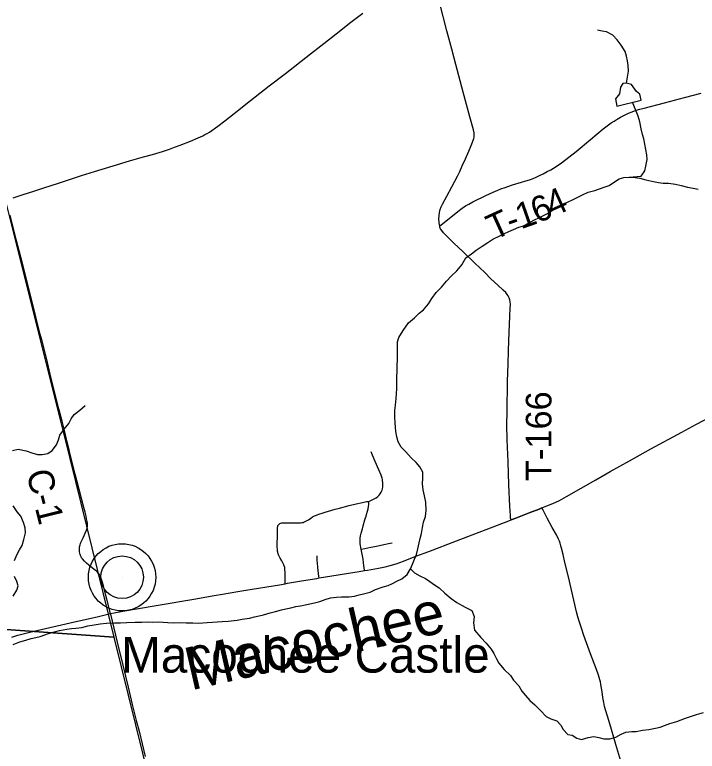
# Model space of a CAD drawing. Extents: x 0 to 1101, y 0 to 440.
# Drawn here: x 842.658 to 844.169, y 377.521 to 379.151 of the extents above; entities that cross this region are included whole.
import ezdxf

# ---------------------------------------------------------------- set-up
doc = ezdxf.new("R2010")
doc.units = 0
for name, color, linetype in [('GM_X_County_Road', 7, 'Continuous'), ('GM_X_County_Road_Text', 7, 'Continuous'), ('GM_X_Minor_Lake', 7, 'Continuous'), ('GM_X_Minor_River', 7, 'Continuous'), ('GM_X_Minor_River_Text', 7, 'Continuous'), ('GM_X_Section', 7, 'Continuous'), ('GM_X_State_Route', 7, 'Continuous'), ('GM_X_Township_Road', 7, 'Continuous'), ('GM_X_Township_Road_Text', 7, 'Continuous'), ('GM_X_Unincorporated', 7, 'Continuous'), ('GM_X_Unincorporated_Location', 7, 'Continuous'), ('GM_X_Unincorporated_Text', 7, 'Continuous')]:
    doc.layers.add(name, color=color, linetype=linetype)

msp = doc.modelspace()

# ---------------------------------------------------------------- linework, layer by layer
at = {"layer": 'GM_X_County_Road'}
for points in [[(842.6544, 378.7458), (842.6772, 378.7533), (842.7008, 378.761), (842.7226, 378.7682), (842.7551, 378.7789), (842.7769, 378.7861), (842.8058, 378.7954), (842.8348, 378.8047), (842.8764, 378.8172), (842.9121, 378.8279), (842.9432, 378.8368), (842.9629, 378.8424), (842.985, 378.8489), (843.0004, 378.8538), (843.0121, 378.858), (843.0243, 378.8626), (843.0475, 378.8717), (843.0641, 378.8787), (843.0691, 378.881), (843.0742, 378.8835), (843.0788, 378.886), (843.0841, 378.8889), (843.0893, 378.8919), (843.0947, 378.8955), (843.1024, 378.9008), (843.1079, 378.9049), (843.1232, 378.9166), (843.1436, 378.9329), (843.1801, 378.9618), (843.2214, 378.9938), (843.2572, 379.0217), (843.3125, 379.0649), (843.3354, 379.083), (843.376, 379.1144), (843.3992, 379.1325), (843.4288, 379.1552)], [(842.8187, 378.0282), (842.8185, 378.0298), (842.8174, 378.0359), (842.8161, 378.0416), (842.814, 378.05), (842.8112, 378.0605), (842.7957, 378.1207), (842.7921, 378.1345), (842.7812, 378.1783), (842.7787, 378.1883), (842.7743, 378.2056), (842.768, 378.2312), (842.763, 378.2515), (842.7561, 378.2789), (842.7369, 378.3557), (842.7289, 378.3882), (842.7181, 378.4316), (842.7147, 378.4442), (842.7088, 378.4671), (842.7016, 378.4952), (842.6907, 378.5397), (842.6746, 378.6038), (842.6616, 378.6538), (842.6482, 378.7076)], [(842.87, 377.8257), (842.862, 377.8576), (842.8592, 377.8686), (842.8545, 377.8871), (842.8518, 377.8972), (842.8498, 377.9037), (842.848, 377.9081), (842.8469, 377.9099), (842.8455, 377.9122), (842.8444, 377.914), (842.8431, 377.9156), (842.8414, 377.9174), (842.8393, 377.9194), (842.8341, 377.9236), (842.822, 377.9333), (842.8173, 377.9373), (842.8125, 377.9419), (842.8082, 377.9467), (842.8063, 377.9492), (842.8049, 377.9516), (842.8037, 377.9541), (842.8027, 377.9569), (842.802, 377.9596), (842.8017, 377.9622), (842.8014, 377.9646), (842.8013, 377.9675), (842.8014, 377.9698), (842.8018, 377.9733), (842.8028, 377.9782), (842.8037, 377.981), (842.8047, 377.9833), (842.8068, 377.9879), (842.8094, 377.9932), (842.8143, 378.0041), (842.8171, 378.0105), (842.8185, 378.0147), (842.819, 378.0175), (842.8193, 378.0195), (842.8193, 378.0217), (842.8192, 378.0237), (842.819, 378.0267), (842.8187, 378.0282)]]:
    msp.add_lwpolyline(points, dxfattribs=at)
at = {"layer": 'GM_X_Minor_Lake'}
for points in [[(844.0447, 378.9623), (844.0422, 378.9757), (844.0344, 378.9814), (844.0232, 378.9968), (844.0119, 379), (844.0039, 378.9989), (843.9989, 378.991), (843.9968, 378.9766), (843.9879, 378.9654), (843.9911, 378.9494)], [(843.9911, 378.9494), (844.0447, 378.9623)]]:
    msp.add_lwpolyline(points, dxfattribs=at)
at = {"layer": 'GM_X_Minor_River'}
for points in [[(844.0121, 378.9999), (844.0164, 379.0268), (844.0158, 379.0394), (844.0148, 379.0493), (844.0123, 379.0595), (844.0091, 379.0698), (844.0006, 379.084), (843.992, 379.0958), (843.9819, 379.1059), (843.9684, 379.1136), (843.9582, 379.1153), (843.948, 379.1173)], [(844.0184, 378.7916), (844.045, 378.7942), (844.0527, 378.8063), (844.0551, 378.8161), (844.0584, 378.8309), (844.0574, 378.8415), (844.0549, 378.8529), (844.0507, 378.8765), (844.0478, 378.886), (844.0449, 378.899), (844.0421, 378.9142), (844.0381, 378.9271), (844.0259, 378.9578)], [(843.3568, 377.8604), (843.3701, 377.8621), (843.3815, 377.8627), (843.3985, 377.8632), (843.4099, 377.8646), (843.4206, 377.8671), (843.4301, 377.8696), (843.4449, 377.8732), (843.4567, 377.8788), (843.4739, 377.885), (843.4845, 377.8882), (843.4941, 377.8927), (843.504, 377.8978), (843.5147, 377.9026), (843.527, 377.9123), (843.5343, 377.9251), (843.539, 377.9349), (843.5434, 377.9462), (843.5473, 377.9568), (843.5505, 377.9689), (843.5533, 377.9821), (843.5557, 377.992), (843.5586, 378.0033), (843.5606, 378.0166), (843.5631, 378.0279), (843.5671, 378.0411), (843.5688, 378.054), (843.5679, 378.0726), (843.5654, 378.0863), (843.5622, 378.1), (843.5609, 378.1129), (843.5618, 378.1254), (843.5612, 378.1387), (843.5546, 378.1509), (843.5464, 378.1605), (843.5355, 378.1709), (843.524, 378.1836), (843.5139, 378.1944), (843.5072, 378.2059), (843.504, 378.2169), (843.5015, 378.2287), (843.5013, 378.2386), (843.5003, 378.2481), (843.4997, 378.2617), (843.4999, 378.2754), (843.5008, 378.2871), (843.5025, 378.3019), (843.5034, 378.3125), (843.5036, 378.3239), (843.5042, 378.3383), (843.5043, 378.3489), (843.5049, 378.363), (843.5054, 378.3994), (843.5053, 378.4142), (843.5058, 378.4275), (843.5082, 378.4373), (843.5179, 378.4523), (843.5299, 378.4692), (843.5433, 378.4808), (843.5533, 378.4905), (843.5633, 378.4984), (843.5737, 378.5115), (843.5811, 378.5232), (843.5911, 378.5363), (843.6027, 378.5487), (843.6142, 378.5614), (843.6242, 378.573), (843.6365, 378.5846), (843.6477, 378.5981), (843.657, 378.6136), (843.6689, 378.6221), (843.6792, 378.63), (843.6926, 378.6393), (843.7052, 378.6471), (843.7163, 378.6545), (843.732, 378.6619), (843.7423, 378.6674), (843.7518, 378.6718), (843.7621, 378.6763), (843.7739, 378.681), (843.7842, 378.6843), (843.7953, 378.6898), (843.8075, 378.6965), (843.8201, 378.7028), (843.8357, 378.7105), (843.8457, 378.7169), (843.8568, 378.7239), (843.869, 378.7306), (843.8831, 378.7376), (843.893, 378.7416), (843.9033, 378.7468), (843.9152, 378.7531), (843.9278, 378.7586), (843.9422, 378.7626), (843.9525, 378.7663), (843.9628, 378.7695), (843.9742, 378.7736), (843.9861, 378.7814), (843.9964, 378.7881), (844.0063, 378.791), (844.0184, 378.7916)], [(844.0184, 378.7916), (844.0317, 378.791), (844.0419, 378.7894), (844.0551, 378.7861), (844.0687, 378.7833), (844.083, 378.7801), (844.0933, 378.7788), (844.105, 378.7783), (844.1205, 378.7762), (844.1334, 378.7737), (844.1473, 378.7697), (844.1602, 378.7677), (844.1707, 378.7652)], [(842.6531, 378.1867), (842.666, 378.1895), (842.6834, 378.1862), (842.6959, 378.1819), (842.7083, 378.1783), (842.7189, 378.1782), (842.7311, 378.1803), (842.7407, 378.187), (842.7507, 378.1993), (842.7554, 378.2107), (842.7582, 378.2205), (842.7679, 378.234), (842.7783, 378.2464), (842.783, 378.2569), (842.7899, 378.2667), (842.8026, 378.2764), (842.8141, 378.2861)], [(842.6576, 377.943), (842.6631, 377.9562), (842.6686, 377.9668), (842.6748, 377.9769), (842.6784, 377.9898), (842.682, 378.0049), (842.681, 378.0156), (842.6774, 378.0274), (842.6719, 378.0415), (842.6633, 378.0511), (842.6544, 378.0641)], [(843.5343, 377.9251), (843.5433, 377.9159), (843.555, 377.9093), (843.5674, 377.9038), (843.5771, 377.8972), (843.5876, 377.8895), (843.5974, 377.8825), (843.6101, 377.8713), (843.6244, 377.8594), (843.6367, 377.8501), (843.6469, 377.8443), (843.657, 377.8392), (843.6698, 377.8326), (843.6753, 377.8192), (843.674, 377.8056), (843.676, 377.7892), (843.6902, 377.7731), (843.7014, 377.7601), (843.713, 377.7474), (843.7189, 377.7374), (843.7244, 377.7256), (843.7299, 377.7157), (843.7419, 377.7022), (843.7553, 377.6884), (843.7624, 377.6784), (843.774, 377.6661), (843.781, 377.6539), (843.7884, 377.6443), (843.7981, 377.6332), (843.8097, 377.6235), (843.8217, 377.6112), (843.8348, 377.5981), (843.8445, 377.5927), (843.8581, 377.5887), (843.8671, 377.5791), (843.8722, 377.5692), (843.8823, 377.5584), (843.8921, 377.5564), (843.9027, 377.5502), (843.9125, 377.5474), (843.9277, 377.5514), (843.9402, 377.5535), (843.9512, 377.5514), (843.9621, 377.5482), (843.9754, 377.5484), (843.9887, 377.5524), (844.0002, 377.5591), (844.0112, 377.5631), (844.0245, 377.5649), (844.034, 377.5651), (844.0477, 377.5676), (844.0621, 377.5693), (844.0765, 377.5725), (844.0868, 377.5743), (844.0963, 377.5779), (844.1081, 377.5827), (844.1237, 377.5867), (844.1333, 377.5907), (844.1432, 377.5944), (844.1561, 377.5991), (844.1675, 377.6024), (844.1831, 377.6068)], [(842.6546, 377.8642), (842.6627, 377.8773), (842.6655, 377.8872), (842.663, 377.8971), (842.6575, 377.9081)], [(842.655, 377.7576), (842.6695, 377.763), (842.6828, 377.767), (842.6942, 377.7707), (842.7052, 377.7732), (842.7147, 377.7749), (842.733, 377.7815), (842.7463, 377.7851), (842.7574, 377.7887), (842.7737, 377.7912), (842.784, 377.7925), (842.7935, 377.7936), (842.8067, 377.7953), (842.82, 377.7985), (842.8337, 377.801), (842.847, 377.8034), (842.8611, 377.8044), (842.8793, 377.8052), (842.8925, 377.8054), (842.9062, 377.8064), (842.9251, 377.8069), (842.9396, 377.8071), (842.9513, 377.8073), (842.9623, 377.8071), (842.9767, 377.8073), (842.9865, 377.8068), (842.9971, 377.8062), (843.0096, 377.8057), (843.0248, 377.8062), (843.0373, 377.8057), (843.0521, 377.8051), (843.0646, 377.8049), (843.0843, 377.8058), (843.0961, 377.8068), (843.1063, 377.8074), (843.1177, 377.808), (843.1306, 377.8089), (843.1503, 377.8109), (843.1614, 377.8134), (843.1781, 377.8159), (843.1891, 377.8187), (843.199, 377.8209), (843.2085, 377.823), (843.2233, 377.8274), (843.2351, 377.8302), (843.2484, 377.8342), (843.2583, 377.836), (843.269, 377.8385), (843.2807, 377.8414), (843.2906, 377.8427), (843.3051, 377.8463), (843.3218, 377.8495), (843.3336, 377.8528), (843.345, 377.8572), (843.3568, 377.8604)]]:
    msp.add_lwpolyline(points, dxfattribs=at)
at = {"layer": 'GM_X_Section'}
for points in [[(842.5276, 378.7981), (842.6237, 378.792), (842.7799, 378.1693), (842.8774, 377.7736), (842.4313, 377.8052)], [(842.4313, 377.8052), (842.8774, 377.7736), (842.9572, 377.4512), (843.1456, 376.7087), (842.3392, 376.7881)]]:
    msp.add_lwpolyline(points, close=True, dxfattribs=at)
at = {"layer": 'GM_X_State_Route'}
for points in [[(843.8248, 378.0596), (843.8362, 378.064), (843.8492, 378.0695), (843.8637, 378.0764), (843.8798, 378.0847), (843.9441, 378.1219), (843.9586, 378.1301), (843.9764, 378.14), (844.0191, 378.1642), (844.0664, 378.1904), (844.1346, 378.2277), (844.1671, 378.2451), (844.2149, 378.2702)], [(843.7567, 378.033), (843.7674, 378.0372), (843.7967, 378.0485), (843.8191, 378.0573), (843.8248, 378.0596)], [(842.87, 377.8257), (842.878, 377.8272), (842.8973, 377.831), (842.9711, 377.8434), (843.0549, 377.8576), (843.0994, 377.8655), (843.1178, 377.8687), (843.1517, 377.8744), (843.1697, 377.8775), (843.244, 377.8896), (843.2567, 377.8919), (843.2622, 377.8929), (843.2929, 377.898), (843.3266, 377.9038), (843.3319, 377.9047), (843.4208, 377.919), (843.4326, 377.921), (843.4394, 377.9221), (843.4636, 377.9263), (843.4778, 377.9293), (843.4895, 377.9325), (843.5022, 377.9362), (843.5185, 377.9422), (843.5462, 377.9527), (843.5746, 377.9633), (843.6358, 377.9866), (843.7519, 378.031), (843.7567, 378.033)], [(842.652, 377.7736), (842.665, 377.7777), (842.6824, 377.7825), (842.7073, 377.7884), (842.7806, 377.805), (842.8435, 377.8196), (842.87, 377.8257), (842.8702, 377.8247)], [(842.8702, 377.8247), (842.8849, 377.7626), (842.8973, 377.7113), (842.909, 377.663), (842.9183, 377.6243), (842.9273, 377.5895), (842.9333, 377.5653), (842.9467, 377.5091)]]:
    msp.add_lwpolyline(points, dxfattribs=at)
at = {"layer": 'GM_X_Township_Road'}
for points in [[(843.651, 378.98), (843.6346, 379.041), (843.6254, 379.0752), (843.6148, 379.1161), (843.5988, 379.1761)], [(843.7567, 378.033), (843.7559, 378.0367), (843.7556, 378.0399), (843.7553, 378.043), (843.7538, 378.0633), (843.7517, 378.1111), (843.7505, 378.1615), (843.7484, 378.2105), (843.7477, 378.2434), (843.7481, 378.2726), (843.7491, 378.3406), (843.7503, 378.3782), (843.7512, 378.4073), (843.7519, 378.4297), (843.7526, 378.4482), (843.7542, 378.4843), (843.7551, 378.5019), (843.7553, 378.51), (843.7549, 378.5161), (843.7539, 378.5207), (843.7525, 378.525), (843.7503, 378.529), (843.7484, 378.532), (843.7449, 378.5363), (843.7392, 378.5419), (843.7276, 378.5531), (843.7124, 378.567), (843.6984, 378.5811), (843.6765, 378.6017), (843.6506, 378.6264), (843.6305, 378.6457), (843.613, 378.6626), (843.6075, 378.6686), (843.6033, 378.6741), (843.6009, 378.6779), (843.5994, 378.6814), (843.5988, 378.6839), (843.5983, 378.6857), (843.5974, 378.692), (843.5971, 378.6989), (843.5975, 378.707), (843.5985, 378.7139), (843.6, 378.72), (843.6021, 378.7259), (843.605, 378.7322), (843.6144, 378.7498), (843.6256, 378.7704), (843.6379, 378.7941), (843.6431, 378.8047), (843.6489, 378.817), (843.6557, 378.8323), (843.6633, 378.8492), (843.6687, 378.8617), (843.6717, 378.8691), (843.6744, 378.8773), (843.6752, 378.8808), (843.6753, 378.885), (843.6748, 378.8904), (843.6734, 378.897), (843.6656, 378.9258), (843.651, 378.98)], [(843.5988, 378.6839), (843.6012, 378.6858), (843.6427, 378.7191), (843.6485, 378.7233), (843.6561, 378.7282), (843.663, 378.7323), (843.6723, 378.7374), (843.7008, 378.7513), (843.717, 378.7585), (843.7277, 378.7632), (843.7344, 378.7659), (843.7436, 378.7694), (843.7498, 378.7716), (843.76, 378.7747), (843.7798, 378.7808), (843.7895, 378.7836), (843.7976, 378.7861), (843.8056, 378.789), (843.8121, 378.792), (843.8195, 378.7953), (843.8281, 378.7996), (843.8367, 378.8042), (843.8445, 378.8084), (843.8504, 378.8118), (843.8564, 378.8155), (843.8684, 378.8238), (843.9008, 378.8491), (843.9328, 378.875), (843.961, 378.8986), (843.9695, 378.9055), (843.9787, 378.9121), (843.9848, 378.9161), (843.9917, 378.9204), (843.9989, 378.9245), (844.0052, 378.928), (844.0108, 378.9307), (844.0169, 378.9334), (844.0246, 378.9365), (844.034, 378.9399), (844.042, 378.9424), (844.0513, 378.945), (844.0963, 378.9565), (844.1409, 378.968), (844.1777, 378.9775)], [(843.2567, 377.8919), (843.2567, 377.895), (843.2568, 377.9012), (843.2569, 377.9118), (843.2569, 377.9171), (843.2564, 377.9236), (843.2558, 377.9275), (843.2548, 377.9316), (843.2539, 377.9339), (843.2527, 377.9366), (843.2495, 377.9425), (843.2456, 377.9487), (843.2433, 377.9529), (843.2418, 377.9559), (843.2412, 377.9581), (843.2403, 377.962), (843.2401, 377.9637), (843.2399, 377.9652), (843.2396, 377.9681), (843.2394, 377.9731), (843.2397, 378.0043), (843.2396, 378.0111), (843.2397, 378.0142), (843.24, 378.0168), (843.2402, 378.0185), (843.2408, 378.0208), (843.2419, 378.0224), (843.2432, 378.0238), (843.245, 378.025), (843.2474, 378.026), (843.2492, 378.0265), (843.2515, 378.0268), (843.2529, 378.0269), (843.2561, 378.027), (843.2676, 378.0268), (843.2856, 378.0265), (843.2909, 378.0268), (843.2937, 378.0271), (843.2964, 378.0278), (843.2989, 378.0287), (843.3014, 378.0299), (843.3042, 378.0314), (843.3081, 378.0336), (843.3133, 378.0371), (843.3174, 378.0397), (843.322, 378.042), (843.326, 378.0438), (843.3311, 378.0461), (843.3384, 378.0484), (843.3452, 378.0507), (843.3526, 378.0529), (843.3598, 378.0548), (843.3678, 378.057), (843.3768, 378.0593), (843.3985, 378.065), (843.4141, 378.0687), (843.4276, 378.0718), (843.4369, 378.0737), (843.4415, 378.0743), (843.4453, 378.0754), (843.4481, 378.0766), (843.4512, 378.0781), (843.4553, 378.0805), (843.4584, 378.0824), (843.4617, 378.0848), (843.4631, 378.0862), (843.465, 378.0883), (843.4672, 378.0911), (843.4693, 378.0945), (843.4712, 378.0989), (843.4723, 378.1022), (843.4729, 378.1062), (843.4732, 378.1101), (843.473, 378.115), (843.4723, 378.1207), (843.4719, 378.123), (843.4713, 378.1254), (843.4705, 378.128), (843.469, 378.1324), (843.4642, 378.1438), (843.4613, 378.1505), (843.4535, 378.1678), (843.4486, 378.1801), (843.4472, 378.1836)], [(843.4326, 377.921), (843.4317, 377.9276), (843.4312, 377.9312), (843.4291, 377.9461), (843.4258, 377.9647), (843.4251, 377.9682), (843.4242, 377.9723), (843.4233, 377.9769), (843.423, 377.9801), (843.4227, 377.9823), (843.4226, 377.9851), (843.4226, 377.988), (843.4229, 377.9928), (843.4238, 377.998), (843.4252, 378.0035), (843.4276, 378.0137), (843.4294, 378.0203), (843.4334, 378.0332), (843.4349, 378.038), (843.436, 378.0415), (843.437, 378.0451), (843.439, 378.0523), (843.4403, 378.0577), (843.4411, 378.0626), (843.4417, 378.067), (843.4419, 378.0704), (843.4415, 378.0743)], [(843.8248, 378.0596), (843.8191, 378.0573), (843.7967, 378.0485), (843.7674, 378.0372), (843.7567, 378.033)], [(843.9828, 377.5564), (843.9806, 377.5642), (843.9776, 377.5743), (843.97, 377.5984), (843.9665, 377.6104), (843.9639, 377.6203), (843.9622, 377.6288), (843.9603, 377.6398), (843.9583, 377.6526), (843.9558, 377.6686), (843.9547, 377.6744), (843.9536, 377.6789), (843.9505, 377.6897), (843.9461, 377.7019), (843.9324, 377.7365), (843.9182, 377.7773), (843.9124, 377.7934), (843.9072, 377.8088), (843.9046, 377.8188), (843.9018, 377.8297), (843.8955, 377.8555), (843.8838, 377.907), (843.8759, 377.9392), (843.8719, 377.9568), (843.8684, 377.9709), (843.8671, 377.9759), (843.8653, 377.9819), (843.8637, 377.9861), (843.8619, 377.9906), (843.8574, 378.0001), (843.8481, 378.0164), (843.8367, 378.0372), (843.8276, 378.0544), (843.8248, 378.0596)], [(843.4251, 377.9682), (843.4328, 377.9698), (843.4462, 377.9725), (843.4589, 377.9753), (843.4753, 377.9787), (843.4892, 377.9816), (843.4935, 377.9824)], [(843.3319, 377.9047), (843.3315, 377.908), (843.3291, 377.9281), (843.3281, 377.9382), (843.3278, 377.9425), (843.3277, 377.9451), (843.3274, 377.9503), (843.3273, 377.954)], [(844.2634, 377.1758), (844.1659, 377.1804), (844.1071, 377.1834), (844.0968, 377.1839), (844.0911, 377.1848), (844.0863, 377.1864), (844.0825, 377.1886), (844.0792, 377.1915), (844.0766, 377.1951), (844.0751, 377.1985), (844.0736, 377.203), (844.0714, 377.2124), (844.0623, 377.2511), (844.0546, 377.2825), (844.0464, 377.3144), (844.0384, 377.3463), (844.0286, 377.3847), (844.0073, 377.4686), (844.004, 377.4823), (843.9973, 377.5063), (843.9885, 377.536), (843.9828, 377.5564)]]:
    msp.add_lwpolyline(points, dxfattribs=at)
at = {"layer": 'GM_X_Unincorporated'}
for radius in [0.0744, 0.0472]:
    msp.add_circle((842.8958, 377.9062), radius, dxfattribs=at)
at = {"layer": 'GM_X_Unincorporated_Location'}
msp.add_line((842.8958, 377.9062), (842.8958, 377.9062), dxfattribs=at)

# ---------------------------------------------------------------- texts
at = {"layer": 'GM_X_County_Road_Text'}
msp.add_text('C-1', height=0.05682, rotation=283.9242, dxfattribs=at).set_placement((842.6835, 378.1381))
at = {"layer": 'GM_X_Minor_River_Text'}
msp.add_text('Macochee', height=0.0947, rotation=12.9756, dxfattribs=at).set_placement((843.0475, 377.6553))
at = {"layer": 'GM_X_Township_Road_Text'}
for s, height, rotation, p in [('4', 0.0568, 24.0927, (843.8487, 378.703)), ('6', 0.0568, 22.1966, (843.8144, 378.6889)), ('1', 0.0568, 19.2446, (843.7783, 378.6763)), ('T', 0.0568, 24.487, (843.7189, 378.6514)), ('-', 0.0568, 19.3409, (843.7563, 378.6686)), ('T-166', 0.05682, 90, (843.8463, 378.1193))]:
    msp.add_text(s, height=height, rotation=rotation, dxfattribs=at).set_placement(p)
at = {"layer": 'GM_X_Unincorporated_Text'}
msp.add_text('Macochee Castle', height=0.078977, rotation=0, dxfattribs=at).set_placement((842.8935, 377.6951))

doc.saveas('drawing.dxf')
